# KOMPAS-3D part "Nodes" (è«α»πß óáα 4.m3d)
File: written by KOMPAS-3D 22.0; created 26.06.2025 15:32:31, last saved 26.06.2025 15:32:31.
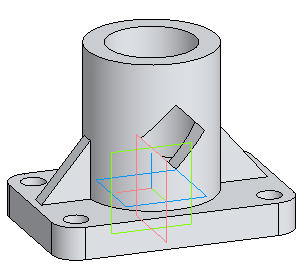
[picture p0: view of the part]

Document properties: Автор: Helen; Полное имя файла: D:\MY\WORK\MPEI\ППЭ_2025-2026\Варианты\Вар 4 СБ\Корпус вар 4.m3d

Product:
- Part/product: Nodes

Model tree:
1. Операция без истории:1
